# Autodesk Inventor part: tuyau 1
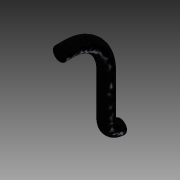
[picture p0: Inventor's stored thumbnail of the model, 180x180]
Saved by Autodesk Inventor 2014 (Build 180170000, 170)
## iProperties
Created: 2015-09
Part Number: tuyau 1
Material: Générique
Document SubType Name: Modeling
Designer: OL
Density: 1 g/cm^3
Appearance: Par défaut
Author: OL
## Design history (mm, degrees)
sketch "Esquisse1"
  geometry: L1 (0, 0)-(0, 0); L2 (-15, 15)-(-15, 60); L3 (-55, 100)-(-65, 100); A1 r 15 centre (0, 15) between (-15, 15) and (0, 0); A2 r 40 centre (-55, 60) between (-15, 60) and (-55, 100); 2 further points
  constraints: 6 end point, 4 point on circle, 4 point on line, 4 tangent, 2 centre point, 1 horizontal, 1 parallel, 1 perpendicular
  dimensions: "d0" = 15 distance of L1.start point (-15, 0); "d1" = 100 distance of point (-15, 0) point (-15, 100); "d2" = 50 distance of point (-15, 100) L3.end; "d3" = 15 radius of A1; "d7" = 40 radius of A2
sketch "Esquisse2"
  geometry: C1 r 7.5 at (0, 0); 1 further point
  constraints: 1 centre point, 1 coincident
  dimensions: "d4" = 15 diameter of C1
feature "Balayage1" sketch "Esquisse1", "Esquisse2" dims "d6" = 0
node "Solide1"
